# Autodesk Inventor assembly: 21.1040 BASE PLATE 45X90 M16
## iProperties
Created: 2007-03
Part Number: 21.1040 BASE PLATE 45X90 M16
Document SubType Name: Assembly
Designer: Andy Moles
Mass: 175.563 g
Surface Area: 152.847 cm^2
Volume: 57.8984 cm^3
Density: 3.03226 g/cm^3
Author: Andy Moles
